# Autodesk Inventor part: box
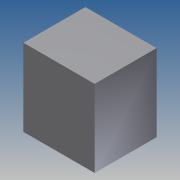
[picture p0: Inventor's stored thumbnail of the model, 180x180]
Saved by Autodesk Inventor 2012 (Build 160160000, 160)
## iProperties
Created: 2012-04
Part Number: box
Material: Default
Document SubType Name: Modeling
Designer: win32
Mass: 2560.27 g
Surface Area: 1127.62 cm^2
Volume: 2560.27 cm^3
Density: 1 g/cm^3
Author: win32
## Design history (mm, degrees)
sketch "Sketch1"
  geometry: L1 (23.828, -236.136)-(-115.735, -236.136); L2 (-115.735, -236.136)-(-115.735, -114.847); L3 (-115.735, -114.847)-(23.828, -114.847); L4 (23.828, -114.847)-(23.828, -236.136)
  constraints: 8 end point, 2 parallel, 1 horizontal, 1 perpendicular
extrude "Extrusion1" new body sketch "Sketch1" distance "d0" = 151.25; taper "d1" = 0 deg
body "Solid1"
